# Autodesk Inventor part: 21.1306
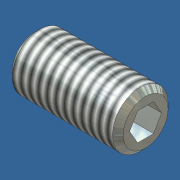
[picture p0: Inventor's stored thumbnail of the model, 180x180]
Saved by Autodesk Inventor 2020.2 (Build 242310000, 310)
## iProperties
Created: 2006-02
Part Number: 21.1306
Material: Steel, Mild
Description: M8x10 Set Screw With Flat Point Din 913
Document SubType Name: Modeling
Standard: DIN 913
Designer: Andy Moles
Standards Organization: DIN
Language: en-US
Size Designation: M8 x 16
Categories: <MemberInstance><Categories><Category DisplayName="Fasteners" InternalName="e4da775c-781d-43d5-af7c-5136215cf5a6" Mnemonic="FSTN"><Category DisplayName="Bolts"
Density: 7.85 g/cm^3
Mass: 3.23653 g
Surface Area: 4.00801 cm^2
Volume: 0.412297 cm^3
Appearance: Zinc
Author: Andy Moles
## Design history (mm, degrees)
sketch "Sketch1"
  geometry: L1 (0, 0)-(3.667, 0); L2 (10, 2.309)-(10, 4); L3 (10, 4)-(0, 4); L4 (10, 2.309)-(5, 2.309); L5 (5, 2.309)-(3.667, 0); L6 (0, -0.8)-(0, 4.8) reference; L7 (0, 4)-(0, 0)
  constraints: 13 end point, 3 parallel, 1 collinear, 1 perpendicular, 1 point on line
  dimensions: "d0" = 5 distance of L2.start L4.end (= INTI); "d1" = 60 deg angle of L5 L1; "d2" = 8 diameter of L3 L1 (= NND); "d3" = 4.6188 diameter of L4 L1 (= 1.1547 x SW); "d5" = 10 distance from line of L2 L3.end (= NLG)
revolve "Body" sketch "Sketch1" stored, may be unused: angle "d6" = 90 deg
sketch "Sketch2"
  geometry: L1 (-1.155, 2)-(1.155, 2); L2 (1.155, 2)-(2.309, 0); L3 (2.309, 0)-(1.155, -2); L4 (1.155, -2)-(-1.155, -2); L5 (-1.155, -2)-(-2.309, 0); L6 (-2.309, 0)-(-1.155, 2); 3 further points
  constraints: 12 end point, 1 coincident, 1 horizontal, 13 other
extrude "Slot" join sketch "Sketch2" taper "d7" = 0 deg; stored distance "d21" = 10
workaxis "Work Axis1"
workplane "Work Plane1"
body "Solid1"
feature "Thread" dims "d8" = 10 (= NLG), "d9" = 0
chamfer "Chamfer1" distance "d10" = 0.76681 (= -0.5 x GD1 + 0.5 x NND); stored, may be unused: angle "d11" = 45 deg (= FAWI), second distance "d34" = 0.76681 (= -0.5 x GD1 + 0.5 x NND)
chamfer "Chamfer2" distance "d12" = 0.76681 (= -0.5 x GD1 + 0.5 x NND); stored, may be unused: angle "d13" = 45 deg (= FAWI), second distance "d35" = 0.76681 (= -0.5 x GD1 + 0.5 x NND)
other parameters: "NND" = 8 [user parameter; used in 5 equation terms], "NLG" = 10 [user parameter; used in 2 equation terms], "INTI" = 5 [user parameter; used in 1 equation term], "FAWI" = 45 deg [user parameter; used in 2 equation terms], "SW" = 4 [user parameter; used in 2 equation terms], "GD1" = 6.46637 (= THREADDIA - 1.2269 x PTC) [user parameter; used in 4 equation terms], "d4" = 0, "SPD" = 5.5 [user parameter], "d33" = 0, "d36" = 0, "GUL" = 0.76681 (= 0.61345 x PTC) [user parameter], "TPU" = 8 (computed from PTC) [user parameter], "TOA" = 30 deg [user parameter], "THREADDIA" = 8 [user parameter; used in 1 equation term], "PTC" = 1.25 [user parameter; used in 4 equation terms], "FAWI1" = 45 deg [user parameter], "GAL" = 0.76681 (= 0.61345 x PTC) [user parameter], "E0" = 4.62 (= 1.155 x SW) [user parameter]
